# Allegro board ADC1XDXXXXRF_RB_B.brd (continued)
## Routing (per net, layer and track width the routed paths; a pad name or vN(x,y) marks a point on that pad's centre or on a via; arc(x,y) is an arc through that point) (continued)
V4_TCK: length 71.7
  TOP w0.102: v1(124.71,85.74) 125.21,86.25 U5.W12
  TOP w0.14: U14.20 v1(150.84,37.35)
  SIG1 w0.152: v1(124.71,85.74) 124.71,85.73 124.21,85.23 124.21,76.25 130.57,69.89 v1(141.96,69.89)
  SIG3 w0.152: v1(141.96,69.89) J6.4 146.72,51 148.12,51 150.84,48.27 v1(150.84,37.35)
V4_TDI: length 30.9
  TOP w0.14: U14.19 v1(150.16,37.85) ; R43.1 J6.5
  SIG3 w0.152: v1(150.16,37.85) 150.16,47.44 147.4,50.21 144.97,50.21 J6.5
V4_TDO: length 45.4
  TOP w0.102: v1(126.71,84.74) 126.22,85.23 U5.Y13
  SIG1 w0.152: v1(128.71,70.66) 128.72,70.66 129.99,69.39 v1(144.16,69.39) ; v1(128.71,77.39) 128.22,77.88 128.22,83.25 126.72,84.74 v1(126.71,84.74)
  SIG3 w0.152: v1(128.71,77.39) v1(128.71,70.66) ; J6.3 144.16,56.1 v1(144.16,69.39)
V4_TMS: length 73.7
  TOP w0.102: v1(123.71,84.74) 124.21,85.24 U5.Y11
  TOP w0.14: v1(152.18,36.86) 152.19,36.85 U14.21
  SIG1 w0.152: v1(123.71,76.01) 124.66,75.06 124.66,73.63 129.38,68.92 v1(147.05,68.92)
  SIG3 w0.152: v1(147.05,68.92) 147.05,55.76 J6.2 152.18,50.61 v1(152.18,36.86) ; v1(123.71,84.74) 123.71,84.74 123.21,84.24 123.21,76.51 v1(123.71,76.01)
VIN: length 73.2
  TOP w0.305: 90.35,158.32 90.35,156.06 v2(90.4,156.01) ; 90.35,158.32 90.35,159.2 90.34,159.2 U23.15 ; 90.35,158.32 90.99,158.32 91,158.33 91,159.36 90.99,159.37 U23.16 ; 109.43,195.94 108.76,195.94 108.76,195.93 U13.14 ; 109.43,195.94 109.76,195.94 ; 109.43,195.94 109.43,194.57 U13.13 ; 91,167.62 91,165.82 90.99,165.82 U23.5 ; 91,167.62 90.35,167.62 90.35,167.62 90.35,166.07 90.34,166.07 U23.6 ; 91,167.62 C269.1 ; 110.06,195.94 109.76,195.94 ; 110.06,195.94 110.71,195.94 U13.11 ; 110.06,195.94 110.06,194.57 U13.12 ; 109.76,195.94 109.76,196.11 ; U29.3 84.84,194.14 85.27,193.72 v2(85.27,192.24) U29.1 ; U16.4 131.28,194.61 131.18,194.72 131.18,195.45 131.4,195.67 131.93,195.67 ; 131.93,195.67 U16.3 ; 131.93,195.67 C193.1 ; v2(111.08,196.69) v2(108.46,196.69)
  TOP w0.508: U22.4 C229.1 ; C229.1 160.61,199.27 v2(160.61,199.26) ; C229.1 C228.1 ; C228.1 158.82,199 v2(158.81,198.99) ; C228.1 157.47,200.14 v2(157.47,200.15) ; C193.1 131.97,196.49 v2(131.98,196.5) 131.97,196.5 C192.1 131.97,198.58 v2(131.98,198.58) ; v2(189.27,200.1) 189.27,200.11 C207.1 ; 109.76,196.11 109.76,196.69 ; C207.1 C208.1 ; C207.1 190.61,199.08 v2(190.6,199.07) ; C208.1 192.35,199.11 v2(192.34,199.1) ; C208.1 U18.4 ; v2(89.67,168.95) 89.67,168.95 C269.1
  TOP w0.61: C159.1 109.74,197.67 ; 109.74,197.67 v2(111.08,197.67) v2(111.08,196.69) ; 109.74,197.67 v2(108.46,197.67) v2(108.46,196.69)
  TOP w0.635: v2(89.67,168.95) 88.14,168.95 C158.1 87.12,168.95 v2(85.59,168.95)
  TOP w0.762: v2(81.48,176.57) 81.49,176.57 L4.2 ; C160.1 85.35,177.82 v2(85.35,177.81) ; C160.1 84.04,176.52 v2(84.04,176.51) ; C160.1 82.47,177.82 v2(82.47,177.81) 82.46,177.82 L4.2 ; L4.2 81.49,178.96 v2(81.48,178.96)
  BOTTOM w0.305: v1(110.16,183.81) 109.83,184.13 109.83,184.24 109.72,184.36 R82.2
  BOTTOM w0.61: C187.1 190.78,199.1 v2(192.34,199.1) ; v2(189.27,200.1) 189.27,199.07 v2(190.6,199.07)
  vias: v2(88.49,157) v2(88.49,156.01)
VINI+: length 24
  TOP w0.102: v1(201.43,93.86) 201.16,94.13 199.74,94.13 U1.H1 ; J7.3 v1(209.27,79.07)
  SIG1 w0.102: v1(201.43,93.86) 201.73,94.16 202.12,94.16 207.96,85.22 207.96,85.21 208.03,85.14 208.16,85.02 209.13,85.02 209.27,84.88 v1(209.27,79.07)
VINI-: length 24
  TOP w0.102: v1(209.27,91.06) 209.27,91.06 211.03,91.06 211.2,90.89 J8.3 ; v1(201.43,94.69) 201.13,94.38 199.75,94.38 U1.J1
  SIG1 w0.102: v1(209.27,91.06) 209.27,85.36 209.13,85.22 208.24,85.22 208.18,85.29 208.13,85.33 202.23,94.36 201.76,94.36 v1(201.43,94.69)
VINQ+: length 24
  TOP w0.102: 211.2,114.52 v1(209.27,114.52) ; U1.N1 199.75,99.46 201.13,99.46 v1(201.43,99.77)
  TOP w0.14: J9.3 211.2,114.52
  SIG1 w0.102: v1(201.43,99.77) 201.76,99.44 201.96,99.44 202.09,99.64 208.02,108.72 209.17,108.72 209.27,108.82 v1(209.27,114.52)
VINQ-: length 24
  TOP w0.102: v1(201.43,98.91) 201.14,99.21 199.74,99.21 U1.M1 ; 211.2,102.7 v1(209.27,102.7)
  TOP w0.14: J10.3 211.2,102.7
  SIG1 w0.102: v1(201.43,98.91) 201.75,99.23 202.08,99.23 202.26,99.54 208.13,108.52 209.15,108.52 209.27,108.4 v1(209.27,102.7)
ADC_PWR: length 5.9
  TOP w0.102: R59.1 R58.2 137.72,82.74 137.23,82.25 U5.AC24
ADC_TDIODE+: length 53.2
  TOP w0.102: U1.E2 198,89.81 198.54,89.27 v1(198.58,89.27) ; v1(167.67,58.48) 167.37,58.18 167.16,58.18 167.06,58.28 167.06,58.62 166.95,58.72 C76.2 166.33,58.57 U8.7
  SIG1 w0.102: v1(167.67,58.48) 167.97,58.18 175.11,58.18 199.14,82.21 199.14,88.72 198.8,89.05 198.8,89.06 198.59,89.27 v1(198.58,89.27)
ADC_TDIODE-: length 130.2
  TOP w0.102: U5.G13 v1(126.71,97.75) ; U8.5 166.33,57.57 C76.1 166.95,57.43 167.06,57.53 167.06,57.87 167.11,57.92 167.42,57.92 v1(167.67,57.68) ; v1(197.33,90.45) 196.7,91.08 U1.F3
  SIG1 w0.102: v1(167.67,57.68) 167.97,57.98 175.19,57.98 199.34,82.13 199.34,88.8 199,89.14 199,89.46 198.74,89.72 198.06,89.72 v1(197.33,90.45)
  SIG2 w0.102: v1(167.67,57.68) 167.26,58.08 167.08,58.08 166.92,58.24 166.92,64.7 153.79,77.83 153.79,77.87 133.88,77.87 133.32,78.43 133.32,95.92 133.32,95.92 133.32,95.92 133.32,96.99 132.96,97.35 132.79,97.35 127.11,97.35 126.71,97.75 v1(126.71,97.75)
  BOTTOM w0.102: v1(167.67,57.68) 167.51,57.83 166.68,57.83 166.62,57.77 C75.1
CAL: length 157.6
  TOP w0.102: 138.71,80.77 138.24,81.24 U5.AD25
  TOP w0.14: 138.71,80.77 139.4,80.77 139.75,80.42 139.75,78.49 143.76,74.48 163.37,74.48 170.56,81.67 v1(191.13,81.67)
  SIG3 w0.14: v1(191.13,81.67) 192.9,83.43 192.9,91.55 192.9,91.55
  SIG3 w0.152: J4.29 154.83,144 154.83,141.87 163.22,133.47 185.89,133.47 186.94,132.42 186.94,114.87 189.79,112.02 193,112.02 194.17,110.86 194.17,92.82 v1(193.82,92.47) 192.9,91.55
  BOTTOM w0.152: R128.1 v1(193.82,92.47)
CALDLY: length 65
  TOP w0.14: J4.20 159.9,144.01 R113.2
  SIG3 w0.152: v1(193.44,113.92) 191.1,116.26 191.1,134.24 189.46,135.88 167.14,135.88 162.45,140.57 162.45,144 161.18,145.28 J4.20
  BOTTOM w0.14: v1(193.44,113.92) 193.44,112.16 R5.1
CALRUN: length 68.9
  TOP w0.102: 193.6,85.44 U1.B5 ; U5.AF23 136.22,78.69
  TOP w0.14: 193.6,85.44 193.6,80.85 192.71,79.96 172.85,79.96 165.97,73.08 141.71,73.08 136.22,78.58 136.22,78.69
CLK+: length 25.5
  TOP w0.102: C341.2 202.06,122.74 v1(201.98,122.66) ; v1(203.64,107.46) 203.34,107.16 203.34,106.73 202.15,105.54 198.45,105.54 U1.U2
  SIG3 w0.102: v1(203.64,107.46) 203.32,107.78 203.32,114.35 204.99,116.02 204.99,119.07 204.99,119.24 202.59,121.65 201.99,121.65 201.66,121.98 201.66,122.33 v1(201.98,122.66)
CLK-: length 24.9
  TOP w0.102: U1.V1 199.21,106.3 198.86,106.3 198.75,106.2 198.75,105.91 198.87,105.79 202.04,105.79 203.09,106.84 203.09,107.16 v1(202.79,107.46) ; v1(201.13,122.66) 201.05,122.74 C342.2
  SIG3 w0.102: v1(201.13,122.66) 201.45,122.33 201.45,121.9 201.9,121.45 201.92,121.45 202.5,121.45 204.79,119.16 204.79,116.11 203.11,114.43 203.11,114.26 203.11,107.78 v1(202.79,107.46)
CONF_CCLK: length 156.5
  TOP w0.14: R83.2 v1(147.21,41.94) R81.2 146,41.88 R84.1 131.88,41.88 v1(131.75,42.02) ; R17.2 107.63,31.6 108.03,31.99 114.03,31.99 114.9,32.87 130.62,32.87 v1(130.65,32.9) ; R31.1 v1(127.74,112.35)
  SIG3 w0.14: v1(130.65,32.9) 130.65,40.92 v1(131.75,42.02)
  SIG3 w0.152: v1(127.74,112.35) 130.49,112.35 132.73,114.58 153.25,114.58 v1(153.88,113.96)
  BOTTOM w0.14: v1(153.88,113.96) 153.88,55.05 147.21,48.38 v1(147.21,41.94)
CONF_DIN: length 211.5
  TOP w0.102: U5.G12 v1(124.71,98.75)
  TOP w0.14: U14.28 v1(172.81,36.85) ; U2.78 101.55,31.77 102.27,32.49 113.29,32.49 114.53,33.73 v1(128.09,33.73)
  SIG1 w0.152: v1(128.09,33.73) 169.69,33.73 v1(172.81,36.85)
  SIG2 w0.152: v1(124.71,112.88) 124.23,112.4 124.23,99.24 v1(124.71,98.75)
  SIG3 w0.152: v1(124.71,112.88) 130.06,112.88 132.19,115.01 158.24,115.01 v1(163.8,109.45)
  BOTTOM w0.14: v1(172.81,36.85) 168.73,40.92 168.73,104.52 v1(163.8,109.45)
CONF_DONE: length 198.2
  TOP w0.102: U5.H14 127.22,97.26 v1(127.71,97.75)
  TOP w0.14: v1(127.22,111.65) 118.74,111.65 118.4,111.99 117.21,111.99 R29.2 ; U14.13 150.7,40.85 149.14,39.28 v1(145.25,39.28) v1(124.08,39.28) ; U2.115 v1(91.23,47.21)
  SIG2 w0.152: v1(127.22,111.65) 127.22,98.24 127.71,97.75 v1(127.71,97.75)
  SIG3 w0.14: 111.81,46.21 92.23,46.21 v1(91.23,47.21)
  SIG3 w0.152: v1(127.22,111.65) 130.8,111.65 133.07,113.92 v1(152.66,113.92) ; 111.81,46.21 117.15,46.21 v1(124.08,39.28)
  BOTTOM w0.14: v1(145.25,39.28) 145.25,47.65 152.66,55.06 v1(152.66,113.92)
CONF_INITB: length 195.3
  TOP w0.102: U5.G15 128.22,98.26 v1(128.71,98.75)
  TOP w0.14: v1(149.67,42.02) 154.55,42.02 U14.11 ; R34.2 117.3,113.5 121.45,113.5 121.9,113.95 v1(128.25,113.95) ; v1(149.67,35.33) 114.7,35.33 113.07,33.7 105.06,33.7 104.45,33.09 102.13,33.09 101.31,32.27 U2.79
  SIG1 w0.152: v1(128.25,113.95) 128.25,108.68 127.23,107.66 127.23,101.96 128.22,100.97 128.22,99.25 v1(128.71,98.75)
  SIG3 w0.14: v1(154.19,116.23) 131.05,116.23 128.77,113.95 v1(128.25,113.95)
  SIG3 w0.152: v1(149.67,42.02) v1(149.67,35.33)
  BOTTOM w0.14: v1(149.67,42.02) 149.67,49.04 154.67,54.05 154.67,115.74 v1(154.19,116.23)
CS_N: length 85.7
  TOP w0.102: 120.22,78.82 U5.AF7
  TOP w0.14: v1(86.23,24.98) U2.42 ; v1(119.73,72.52) 119.74,72.52 120.22,73 120.22,78.82
  SIG1 w0.152: v1(92.29,72.25) 92.29,60.66 89.83,58.2 89.83,41.98 89.83,41.97 89.83,41.57 89.83,41.56 89.83,28.59 v1(86.23,24.98)
  SIG3 w0.152: v1(92.29,72.25) 92.55,72.52 v1(119.73,72.52)
CY_ADDR0: length 61
  TOP w0.102: 115.2,86.25 114.76,85.8
  TOP w0.14: 114.76,85.8 105.51,85.8 103.85,84.13 103.85,40.6 103.01,39.77 U2.94 ; U5.W2 115.2,86.25
CY_ADDR1: length 59.9
  TOP w0.102: U5.W1 113.39,86.25
  TOP w0.14: U2.95 102.58,40.27 103.35,41.04 103.35,84.86 104.74,86.25 113.39,86.25
CY_ADDR2: length 63.7
  TOP w0.102: v1(119.71,86.74) 119.22,87.23 U5.V6
  TOP w0.14: U2.96 102.19,40.77 102.82,41.4 v1(102.82,48.68)
  SIG1 w0.152: v1(119.71,86.74) 120.15,86.29 120.15,85.5 119.92,85.27 109.37,85.27 102.82,78.71 v1(102.82,48.68)
CY_ADDR3: length 65.1
  TOP w0.102: U5.V5 118.22,87.23 117.73,86.74 v1(117.71,86.74)
  TOP w0.14: v1(102.28,86.74) 102.29,86.74 102.29,41.68 101.88,41.27 U2.97
  BOTTOM w0.14: v1(102.28,86.74) 102.79,87.24 117.2,87.24 v1(117.71,86.74)
CY_ADDR4: length 67.4
  TOP w0.102: v1(119.71,85.74) 120.21,86.25 U5.W7
  TOP w0.14: U2.117 90.23,56.86 90.83,57.45 90.83,81.24 v1(90.83,81.25)
  SIG2 w0.152: v1(90.83,81.25) 91,81.25 95.02,85.27 119.24,85.27 119.71,85.74 v1(119.71,85.74)
CY_ADDR5: length 73
  TOP w0.102: U5.V7 120.21,87.24 v1(120.71,86.74)
  TOP w0.14: v1(91.03,86.69) 90.35,86 90.35,57.83 89.73,57.22 U2.118
  SIG2 w0.152: v1(91.03,86.69) 92.06,85.66 115.02,85.66 115.54,86.18 120.15,86.18 v1(120.71,86.74)
CY_ADDR6: length 68.8
  TOP w0.102: v1(116.71,85.74) 116.72,85.74 U5.W4
  TOP w0.14: v1(89.87,86.25) 89.87,86.25 89.87,58.12 89.23,57.48 U2.119
  SIG3 w0.152: v1(89.87,86.25) 116.19,86.25 v1(116.71,85.74)
CY_ADDR7: length 67.6
  TOP w0.102: v1(115.7,85.74) 115.72,85.74 U5.W3
  TOP w0.14: v1(89.31,85.78) 89.31,61.03 89.31,61.03 89.31,60.63 89.31,60.63 89.31,58.36 88.73,57.78 U2.120
  SIG3 w0.152: v1(115.7,85.74) 115.67,85.78 v1(89.31,85.78)
CY_ADDR8: length 72.8
  TOP w0.102: v1(118.71,85.74) 118.71,85.74 U5.W6
  TOP w0.14: v1(85.71,78.66) 85.69,78.64 85.69,45.56 U2.126
  SIG3 w0.152: v1(85.71,78.66) 116.66,78.66 118.24,80.24 118.24,85.27 v1(118.71,85.74)
CY_ADDR9: length 72.6
  TOP w0.102: v1(117.71,85.74) 117.71,85.74 117.72,85.74 U5.W5
  TOP w0.14: v1(85.23,79.27) U2.127
  SIG3 w0.152: v1(85.23,79.27) 116.23,79.27 117.21,80.26 117.21,85.23 v1(117.71,85.74)
CY_ADDR10: length 68.4
  TOP w0.102: 114.76,84.76 115.22,85.22 U5.Y2
  TOP w0.14: 114.76,84.76 110.36,84.76 v1(109.35,83.74) ; U2.128 84.73,51.1 84.73,51.1 v1(84.73,82.19)
  SIG3 w0.152: v1(109.35,83.74) 86.28,83.74 v1(84.73,82.19)
CY_ADDR11: length 80.8
  TOP w0.102: 113.77,85.24 U5.Y1
  TOP w0.14: U2.21 v1(88.33,33.77) ; 113.77,85.24 107.39,85.24 104.93,82.78
  TOP w0.152: v1(104.93,82.73) 104.93,82.78
  SIG1 w0.133: v1(88.33,33.77) 88.33,81.86 v1(88.54,82.07)
  SIG3 w0.152: v1(88.54,82.07) 89.2,82.73 v1(104.93,82.73)
CY_ADDR12: length 84.2
  TOP w0.102: v1(116.71,83.74) 116.72,83.74 U5.AA4
  TOP w0.14: U2.22 v1(87.82,33.27)
  SIG1 w0.133: v1(87.82,33.27) 87.82,82.44 v1(88.59,83.21)
  SIG3 w0.152: v1(116.71,83.74) 116.2,83.24 88.61,83.24 v1(88.59,83.21)
CY_ADDR13: length 84.4
  TOP w0.102: v1(115.71,83.75) 115.73,83.75 U5.AA3
  TOP w0.14: U2.23 v1(87.29,32.77)
  SIG1 w0.133: v1(88.62,84.28) 87.29,82.95 v1(87.29,32.77)
  SIG3 w0.152: v1(115.71,83.75) 115.18,84.28 v1(88.62,84.28)
CY_ADDR14: length 86.5
  TOP w0.102: U5.Y4 116.72,84.74 v1(116.71,84.74)
  TOP w0.14: U2.24 v1(86.77,32.27)
  SIG1 w0.133: v1(88.7,85.24) 86.77,83.31 v1(86.77,32.27)
  SIG3 w0.152: v1(88.7,85.24) 116.2,85.24 v1(116.71,84.74)
CY_ADDR15: length 85.7
  TOP w0.102: U5.Y3 115.72,84.74 v1(115.7,84.74)
  TOP w0.14: U2.25 v1(86.23,31.77)
  SIG1 w0.133: v1(86.23,31.77) 86.23,83.49 v1(87.48,84.73)
  SIG3 w0.152: v1(87.48,84.73) 115.7,84.73 v1(115.7,84.74)
CY_CTL3: length 83.2
  TOP w0.102: v1(127.72,79.74) 127.71,79.74 127.22,80.23 U5.AE14
  TOP w0.14: U2.66 113.11,25.77 113.55,26.21 126.82,26.21 127.07,26.46 v1(127.07,28.75)
  SIG1 w0.152: v1(127.07,28.75) 127.07,49.42 128.4,50.75 v1(128.4,55.57)
  SIG3 w0.152: v1(128.4,55.57) 128.23,55.74 128.23,79.23 v1(127.72,79.74)
CY_CTL4: length 80.4
  TOP w0.102: 126.7,79.77 U5.AE13
  TOP w0.14: 126.7,79.77 126.7,78.45 127.27,77.88 127.27,54.64 v1(127.6,54.31) ; U2.67 110.95,26.27 114.68,30 v1(126.55,30)
  SIG1 w0.152: v1(126.55,30) 126.55,49.94 127.6,50.99 v1(127.6,54.31)
CY_CTL5: length 61.9
  TOP w0.102: 122.73,79.76 U5.AE10
  TOP w0.14: v1(122.17,70.93) 122.73,71.49 122.73,79.76 ; U2.98 101.36,41.77 101.72,42.13 v1(101.72,70.93)
  SIG3 w0.152: v1(101.72,70.93) v1(122.17,70.93)
CY_DATA0: length 74.9
  TOP w0.102: 117.22,78.28 U5.AF4
  TOP w0.14: v1(114.77,74.69) 114.77,75.83 117.22,78.28 ; U2.59 v1(94.73,25.55)
  SIG1 w0.152: v1(94.73,25.55) 94.73,42.44 97.89,45.59 v1(97.89,74.69)
  SIG3 w0.152: v1(114.77,74.69) v1(97.89,74.69)
CY_DATA1: length 75
  TOP w0.102: 116.74,79.76 117.22,80.24 U5.AE4
  TOP w0.14: 116.74,79.76 116.74,78.41 114.09,75.76 v1(114.09,75.18) ; U2.60 v1(95.23,26.37)
  SIG1 w0.152: v1(98.48,75.18) 98.48,45.63 95.23,42.39 v1(95.23,26.37)
  SIG3 w0.152: v1(114.09,75.18) v1(98.48,75.18)
CY_DATA2: length 75.7
  TOP w0.102: U5.AD3 v1(115.71,80.73)
  TOP w0.14: U2.61 v1(95.74,27.34)
  SIG1 w0.152: v1(95.74,27.34) 95.74,42.36 98.93,45.55 v1(98.93,80.14)
  SIG3 w0.152: v1(98.93,80.14) 99.16,80.38 106.34,80.38 106.69,80.73 106.74,80.73 106.74,80.73 v1(115.71,80.73)
CY_DATA3: length 75.1
  TOP w0.102: v1(115.7,81.76) 115.74,81.76 U5.AC3
  TOP w0.14: U2.62 v1(96.23,26.36)
  SIG1 w0.133: 110.98,79.74 v1(110.86,79.74)
  SIG1 w0.152: v1(96.23,26.36) 96.23,40.58 99.9,44.24 v1(99.9,79.74) ; 110.98,79.74 113,81.76 v1(115.7,81.76)
  SIG3 w0.152: v1(110.86,79.74) v1(99.9,79.74)
CY_DATA4: length 75.5
  TOP w0.102: 119.22,78.8 U5.AF6
  TOP w0.14: v1(118.5,72.01) 119.22,72.73 119.22,78.8 ; U2.63 v1(96.73,25.55)
  SIG1 w0.152: v1(96.73,25.55) 96.73,40.52 100.48,44.26 v1(100.48,71.88)
  SIG3 w0.152: v1(118.5,72.01) 100.61,72.01 v1(100.48,71.88)
CY_DATA5: length 59.2
  TOP w0.102: 118.22,78.83 U5.AF5
  TOP w0.14: U2.86 v1(100.36,35.77) ; 118.22,78.83 118.22,74.78 114.22,70.77 114.22,58.57 112.16,56.52 v1(112.16,35.77)
  SIG3 w0.152: v1(100.36,35.77) v1(112.16,35.77)
CY_DATA6: length 64.5
  TOP w0.102: U5.AA7 120.21,84.24 v1(119.71,83.74)
  TOP w0.14: U2.87 v1(101.18,36.27)
  SIG1 w0.152: v1(111.46,36.27) 111.46,66.88 120.22,75.64 120.22,82.98 120.21,82.99 120.21,83.25 119.71,83.74 v1(119.71,83.74)
  SIG3 w0.152: v1(101.18,36.27) v1(111.46,36.27)
CY_DATA7: length 64.2
  TOP w0.102: U5.Y7 119.72,84.74 v1(119.71,84.74)
  TOP w0.14: v1(100.35,36.79) 99,36.79 U2.88
  SIG1 w0.152: v1(119.71,84.74) 119.22,84.25 119.22,83.98 119.23,83.97 119.23,75.47 110.72,66.96 v1(110.72,36.79)
  SIG3 w0.152: v1(110.72,36.79) v1(100.35,36.79)
CY_FD0: length 97.5
  TOP w0.102: v1(118.71,84.74) 118.72,84.74 U5.Y6
  TOP w0.14: U2.44 87.23,20.17 v1(87.23,20.17)
  SIG1 w0.152: v1(118.71,84.74) 118.26,84.3 118.26,83.54 117.96,83.24 111.4,83.26 107.24,79.1 107.24,20.42 106.47,19.66 v1(106.01,19.66)
  SIG3 w0.152: v1(106.01,19.66) 87.74,19.66 v1(87.23,20.17)
CY_FD1: length 94.8
  TOP w0.102: U5.Y5 117.72,84.74 v1(117.71,84.74)
  TOP w0.14: v1(87.73,20.83) 87.73,20.83 U2.45
  SIG1 w0.152: v1(117.71,84.74) 117.22,84.25 111.46,84.25 106.6,79.39 v1(106.6,20.53)
  SIG3 w0.152: v1(106.6,20.53) 106.33,20.27 88.29,20.27 v1(87.73,20.83)
CY_FD2: length 88.5
  TOP w0.102: 113.73,83.25 U5.AB1
  TOP w0.14: 113.73,83.25 111.03,83.25 107.86,80.08 v1(107.86,76.67) ; U2.46 v1(88.23,21.48)
  SIG1 w0.152: v1(107.86,21.32) v1(107.86,76.67)
  SIG3 w0.152: v1(88.23,21.48) 88.83,20.88 105.01,20.88 105.3,21.17 107.72,21.17 v1(107.86,21.32)
CY_FD3: length 86.7
  TOP w0.102: 113.75,84.24 U5.AA1
  TOP w0.14: U2.47 v1(88.73,22.16) ; v1(106.04,76.61) 106.04,79.47 110.81,84.24 113.75,84.24
  SIG1 w0.152: v1(105.97,22.16) 105.97,76.53 v1(106.04,76.61)
  SIG3 w0.152: v1(105.97,22.16) 105.16,22.16 104.49,21.49 89.4,21.49 v1(88.73,22.16)
CY_FD4: length 81.6
  TOP w0.102: v1(116.71,81.74) 116.72,81.74 U5.AC4
  TOP w0.14: v1(92.25,24.89) 92.23,24.87 U2.54
  SIG1 w0.152: v1(94.26,80.74) 94.26,49.68 92.25,47.67 v1(92.25,24.89)
  SIG3 w0.152: v1(116.71,81.74) 116.71,81.74 116.22,81.25 106.41,81.25 106.08,80.92 94.44,80.92 v1(94.26,80.74)
CY_FD5: length 81.9
  TOP w0.102: v1(116.71,82.74) 116.71,82.75 117.21,83.25 U5.AB4
  TOP w0.14: U2.55 v1(92.73,25.73)
  SIG1 w0.152: v1(92.73,25.73) 92.73,47.62 95.04,49.94 95.04,81.6 v1(95.28,81.84)
  SIG3 w0.152: v1(95.28,81.84) 105.51,81.84 105.93,82.26 116.23,82.26 116.71,82.74 v1(116.71,82.74)
CY_FD6: length 80.3
  TOP w0.102: v1(115.7,82.74) 115.71,82.74 116.22,83.25 U5.AB3
  TOP w0.14: v1(93.22,26.56) 93.23,26.55 U2.56
  SIG1 w0.152: v1(93.22,26.56) 93.22,47.54 95.62,49.94 95.62,81.47 v1(96.41,82.27)
  SIG3 w0.152: v1(96.41,82.27) 105.21,82.27 105.68,82.74 v1(115.7,82.74)
CY_FD7: length 78.5
  TOP w0.102: U5.AB2 115.22,83.24 114.78,82.8
  TOP w0.14: U2.57 93.73,25.66 v1(93.72,25.68) ; v1(111.02,81.74) 112.09,82.8 114.78,82.8
  SIG1 w0.152: v1(96.57,81.39) 96.07,80.89 96.07,46.92 93.72,44.56 v1(93.72,25.68)
  SIG3 w0.152: v1(96.57,81.39) 105.78,81.39 106.13,81.74 v1(111.02,81.74)
CY_FD8: length 57.2
  TOP w0.102: U5.AC5 117.72,81.74 v1(117.71,81.74)
  TOP w0.14: v1(99.4,76.83) 98.98,76.42 98.98,47.12
  TOP w0.152: 98.98,47.12 U2.102
  SIG1 w0.152: v1(117.74,77.65) 118.24,78.16 118.24,81.24 117.74,81.74 v1(117.71,81.74)
  SIG3 w0.152: v1(99.4,76.83) 99.74,77.17 117.26,77.17 v1(117.74,77.65)
CY_FD9: length 57.3
  TOP w0.102: U5.AB5 117.72,82.74 v1(117.71,82.74)
  TOP w0.14: U2.103 97.23,75.18 v1(97.69,75.64)
  SIG1 w0.152: v1(117.71,82.74) 117.71,82.73 117.2,82.22 117.2,80.47 116.24,79.5 v1(116.24,75.64)
  SIG3 w0.152: v1(116.24,75.64) v1(97.69,75.64)
CY_FD10: length 53.7
  TOP w0.102: U5.AC2 115.19,82.25 114.76,81.81
  TOP w0.14: 114.76,81.81 112.79,81.81 111.44,80.47 v1(111.44,77.65) ; v1(97.57,77.65) 96.73,76.81 U2.104
  SIG3 w0.152: v1(111.44,77.65) v1(97.57,77.65)
CY_FD11: length 53.1
  TOP w0.102: 113.82,82.25 U5.AC1
  TOP w0.14: v1(96.83,78.16) 96.24,77.57 U2.105 ; 113.82,82.25 112.44,82.25 110.27,80.08 v1(110.27,78.16)
  SIG3 w0.152: v1(110.27,78.16) v1(96.83,78.16)
CY_FD12: length 59.8
  TOP w0.102: 116.22,78.6 U5.AF3
  TOP w0.14: v1(88.81,59.31) 88.23,58.73 U2.121 ; 116.22,78.6 113.49,75.88 v1(113.49,59.31)
  SIG3 w0.133: v1(88.81,59.31) v1(113.49,59.31)
CY_FD13: length 60.7
  TOP w0.102: 115.75,79.78 116.21,80.24 U5.AE3
  TOP w0.14: v1(113,60.07) 113,76.04 115.72,78.77 115.72,79.76 115.75,79.78 ; v1(88.82,60.07) 87.73,58.99 U2.122
  SIG3 w0.133: v1(88.82,60.07) v1(113,60.07)
CY_FD14: length 61.8
  TOP w0.102: U5.AD2 115.2,81.24 114.71,80.75
  TOP w0.14: v1(88.83,60.83) 87.23,59.23 U2.123 ; v1(112.48,60.83) 112.48,79.66 113.56,80.75 114.71,80.75
  SIG3 w0.133: v1(88.83,60.83) v1(112.48,60.83)
CY_FD15: length 61.1
  TOP w0.102: 113.85,81.24 U5.AD1
  TOP w0.14: v1(88.83,61.62) 86.73,59.52 U2.124 ; 113.85,81.24 113.38,81.24 111.94,79.81 v1(111.94,61.62)
  SIG3 w0.133: v1(88.83,61.62) v1(111.94,61.62)
CY_ID0: length 72.3
  TOP w0.102: v1(121.71,83.74) 122.21,84.24 U5.AA9
  TOP w0.14: U2.72 110.61,28.77 v1(112.11,30.27)
  SIG1 w0.152: v1(121.71,83.74) 122.21,83.24 122.21,74.35 115.28,67.41 115.28,33.44 v1(112.11,30.27)
CY_ID1: length 73
  TOP w0.102: U5.Y9 122.21,85.24 v1(121.71,84.74)
  TOP w0.14: v1(109.76,29.27) 102.35,29.27 102.34,29.27 U2.73
  SIG1 w0.152: v1(117.71,76.83) 117.71,75.44 109.76,67.49 v1(109.76,29.27)
  SIG3 w0.152: v1(121.71,84.74) 121.71,84.74 121.23,84.26 119.43,84.26 119.22,84.05 119.22,81.97 119.23,81.96 119.23,81.56 119.22,81.56 119.22,80.98 119.23,80.97 119.23,80.57 119.22,80.57 119.22,78.34 v1(117.71,76.83)
CY_ID2: length 65.4
  TOP w0.102: v1(117.71,80.74) 117.71,80.75 118.2,81.24 U5.AD5
  TOP w0.14: U2.74 101.3,29.77 101.3,29.77 v1(109.15,29.77)
  SIG1 w0.152: v1(109.15,29.77) 109.15,67.64 117.21,75.7 117.21,79.21 117.71,79.71 v1(117.71,80.74)
CY_ID3: length 65.5
  TOP w0.102: v1(116.71,80.74) 116.73,80.74 117.22,81.23 U5.AD4
  TOP w0.14: v1(108.56,30.27) U2.75
  SIG1 w0.152: v1(116.71,80.74) 116.21,80.24 113.87,80.24 112.4,78.78 112.4,77.57 108.56,73.73 v1(108.56,30.27)
CY_REQ: length 53.6
  TOP w0.102: U5.AB7 120.2,83.25 119.71,82.75 v1(119.71,82.74)
  TOP w0.14: v1(93.22,78.16) 93.22,56.19 92.2,55.18 R13.2
  SIG2 w0.152: v1(93.22,78.16) 93.25,78.2 94.83,78.2 98.89,82.25 119.22,82.25 v1(119.71,82.74)
CY_VALID: length 65.7
  TOP w0.102: v1(121.72,81.74) 122.22,82.24 U5.AC9
  TOP w0.14: U2.114 v1(91.73,49.74)
  SIG1 w0.152: v1(92.74,73.6) 92.74,60.34 91.73,59.33 v1(91.73,49.74)
  SIG3 w0.152: v1(121.72,81.74) 121.72,81.74 121.23,81.25 121.23,79.98 121.23,79.98 121.23,79.58 121.23,79.58 121.23,74.19 120.65,73.6 v1(92.74,73.6)
DCLK_RST+: length 22.4
  TOP w0.102: v1(198.57,106.92) 197.97,106.32 U1.V2
  BOTTOM w0.102: R132.1 204.1,112.21 ; 204.1,112.21 204.1,113.06 206.72,115.67 206.72,119.52 207.34,120.15 R131.2 ; 204.1,112.21 204.1,110.51 ; R133.2 201.45,108.63 ; 201.45,108.63 200.29,108.63 199.12,107.45 198.68,107.45 198.57,107.34 v1(198.57,106.92) ; 201.45,108.63 203.72,108.63 204.1,109.01 204.1,110.51 ; 204.1,110.51 TP4.1
DCLK_RST-: length 22.1
  TOP w0.102: U1.W1 v1(198.63,108.2)
  BOTTOM w0.102: 203.9,110.52 203.9,109.1 203.64,108.83 201.45,108.83 ; 203.9,110.52 203.9,112.21 ; 203.9,110.52 TP3.1 ; R129.2 205.89,120.14 206.51,119.52 206.51,115.75 203.9,113.14 203.9,112.21 ; 203.9,112.21 R130.1 ; 201.45,108.83 200.21,108.83 199.03,107.65 198.73,107.65 198.63,107.75 v1(198.63,108.2) ; 201.45,108.83 R133.1
DCLKI+: length 65.9
  TOP w0.102: v1(159.34,98.05) 159.34,96.88 161.27,94.95 167.77,94.95 168.47,95.64 175.27,95.64 175.8,96.16 U1.K19 ; U5.A16 v1(128.71,104.76)
  SIG3 w0.102: v1(159.34,98.05) 157.45,99.93 157.45,102.26 158.2,103 159.31,103 159.41,103.1 159.41,103.31 159.31,103.41 158.2,103.41 157.98,103.63 157.98,104 158.2,104.22 159.31,104.22 159.41,104.32 159.41,104.53 159.31,104.63 158.2,104.63 157.98,104.85 157.98,106.25 157.44,106.79 128.94,106.79 128.55,106.4 128.55,104.91 v1(128.71,104.76)
DCLKI-: length 65.9
  TOP w0.102: U5.A15 v1(127.71,104.76) ; v1(160.1,98.05) 159.54,97.49 159.54,97.03 161.37,95.2 167.67,95.2 168.36,95.9 174.84,95.9 U1.K20
  SIG3 w0.102: v1(127.71,104.76) 128,104.76 128.35,105.11 128.35,106.49 128.86,106.99 157.52,106.99 158.18,106.33 158.18,104.93 158.29,104.83 159.39,104.83 159.61,104.61 159.61,104.24 159.39,104.02 158.29,104.02 158.18,103.92 158.18,103.71 158.29,103.61 159.39,103.61 159.61,103.39 159.61,103.02 159.39,102.8 158.29,102.8 157.66,102.17 157.66,100.02 159.2,98.48 159.67,98.48 v1(160.1,98.05)
DCLKQ+: length 52.1
  TOP w0.102: U5.A10 123.23,104.24 v1(123.74,104.76)
  SIG3 w0.102: v1(166.14,96.1) 166.32,96.28 166.32,97.21 162,101.53 162,103.3 157.24,108.06 125.86,108.06 123.74,105.95 v1(123.74,104.76)
DCLKQ+_OUT: length 49.7
  TOP w0.102: R162.3 163.53,96.1 162.71,96.91 161.89,96.91 161.67,97.13 161.67,98.68 142.32,118.03 142.32,122.63 138.07,126.87 136.5,126.87 136.4,126.77 DCLKQ+.1
DCLKQ-: length 52.1
  TOP w0.102: v1(123.74,103.76) 123.23,103.25 U5.B10
  SIG3 w0.102: v1(123.74,103.76) 123.74,104.19 123.32,104.6 123.32,104.92 123.54,105.14 123.54,106.04 125.77,108.27 157.32,108.27 162.2,103.39 162.2,101.62 165.84,97.98 v1(166.14,97.98)
DCLKQ-_OUT: length 49.7
  TOP w0.102: DCLKQ-.1 136.4,127.23 136.5,127.13 138.18,127.13 142.57,122.73 142.57,118.14 161.92,98.79 161.92,97.24 161.99,97.17 162.71,97.17 163.53,97.98 R161.3
DCLKQ_N: length 12.1
  TOP w0.102: U1.L20 174.84,97.17 174.33,97.17 174.08,97.42 174.08,97.89 173.82,98.15 173.55,98.15 173.29,97.89 173.29,97.42 173.04,97.17 165.66,97.17 R161.2
DCLKQ_P: length 12.1
  TOP w0.102: U1.L19 175.82,97.43 175.3,96.91 165.66,96.91 R162.2
DDRPHASE: length 64.1
  TOP w0.14: J4.17 162.44,144.01 R28.2
  SIG3 w0.152: J4.17 164.98,144.01 164.98,140.32 168.62,136.68 190.09,136.68 192.15,134.62 192.15,116.77 v1(193.44,115.48)
  BOTTOM w0.14: R3.1 195.02,113.91 v1(193.44,115.48)
DES: length 59.6
  TOP w0.14: R26.2 167.52,144 168.79,145.27 J4.11
  SIG3 w0.152: J4.11 168.79,145.28 170.06,144.01 170.06,140.67 172.22,138.51 191.07,138.51 194.06,135.52 v1(194.06,119.2)
  BOTTOM w0.14: R6.1 191.86,117 v1(194.06,119.2)
DI+0: length 67
  TOP w0.102: U1.B18 v1(178.28,85.37) ; U5.N23 v1(136.67,91.79)
  SIG1 w0.102: v1(136.67,91.79) 136.67,91.79 137.43,92.54 145.56,92.54 145.93,92.18 145.93,85.39 147.56,83.76 163.66,83.76 163.88,83.98 163.88,85.83 163.98,85.93 164.18,85.93 164.28,85.83 164.28,83.98 164.5,83.76 164.87,83.76 165.09,83.98 165.09,85.83 165.2,85.93 165.4,85.93 165.5,85.83 165.5,83.98 165.72,83.76 166.09,83.76 166.31,83.98 166.31,85.83 166.42,85.93 166.62,85.93 166.72,85.83 166.72,83.98 166.94,83.76 167.31,83.76 167.53,83.98 167.53,85.77 167.63,85.87 177.27,85.87 177.74,86.34 178.02,86.34 178.28,86.07 v1(178.28,85.37)
  BOTTOM w0.102: v1(178.28,85.37) R210.1
DI+1: length 67
  TOP w0.102: U5.M21 134.22,93.25 v1(134.72,92.75) ; v1(175.78,85.4) 176.38,86 U1.B19
  SIG2 w0.102: v1(175.78,85.4) 175.18,85.4 174.51,86.07 167.3,86.07 167.08,85.84 167.08,83.25 166.98,83.14 166.58,83.14 166.48,83.25 166.48,85.29 166.26,85.51 165.89,85.51 165.67,85.29 165.67,83.25 165.57,83.14 165.36,83.14 165.26,83.25 165.26,85.29 165.04,85.51 164.67,85.51 164.45,85.29 164.45,83.25 164.35,83.14 164.14,83.14 164.04,83.25 164.04,85.29 163.82,85.51 163.45,85.51 163.23,85.29 163.23,83.25 163.13,83.14 145.74,83.14 144.6,84.28 144.6,89.92 143.17,91.35 136.13,91.35 134.73,92.75 v1(134.72,92.75)
  BOTTOM w0.102: R213.1 175.31,84.81 175.31,84.96 175.75,85.4 v1(175.78,85.4)
DI+2: length 65.9
  TOP w0.102: U1.C19 176.38,87.27 v1(175.76,86.66) ; U5.M23 v1(136.72,93.75)
  SIG1 w0.102: v1(175.76,86.66) 174.71,86.66 174.32,87.05 163.33,87.05 163.11,86.83 163.11,84.55 163.01,84.45 162.81,84.45 162.71,84.55 162.71,86.86 162.49,87.08 162.11,87.08 161.89,86.86 161.89,84.55 161.79,84.45 161.59,84.45 161.49,84.55 161.49,86.86 161.27,87.08 160.9,87.08 160.68,86.86 160.68,84.55 160.57,84.45 160.37,84.45 160.27,84.55 160.27,86.86 160.05,87.08 159.68,87.08 159.46,86.86 159.46,84.55 159.35,84.45 148.37,84.45 147.16,85.66 147.16,92.75 146.64,93.26 137.21,93.26 v1(136.72,93.75)
DI+3: length 66
  TOP w0.102: v1(178.28,89.17) 177.65,88.54 U1.D18 ; v1(138.73,93.75) 138.23,93.25 U5.M25
  SIG1 w0.102: v1(178.28,89.17) 177.59,89.17 177.24,88.82 177.24,88.15 176.4,87.3 173.94,87.3 173.5,87.74 159.2,87.74 159.1,87.64 159.1,85.6 158.88,85.38 158.51,85.38 158.29,85.6 158.29,87.64 158.19,87.74 157.98,87.74 157.88,87.64 157.88,85.6 157.66,85.38 157.29,85.38 157.07,85.6 157.07,87.64 156.97,87.74 156.76,87.74 156.66,87.64 156.66,85.6 156.44,85.38 156.07,85.38 155.85,85.6 155.85,87.64 155.75,87.74 155.54,87.74 155.44,87.64 155.44,85.6 155.23,85.39 148.6,85.39 147.99,85.99 147.99,93.65 147.49,94.15 139.13,94.15 v1(138.73,93.75)
DI+4: length 65.9
  TOP w0.102: U5.L21 134.22,94.24 v1(134.72,93.75) ; U1.D19 176.38,88.54 v1(175.82,87.98)
  SIG2 w0.102: v1(175.82,87.98) 175.15,87.98 174.52,88.62 166.26,88.62 166.04,88.4 166.04,86.71 165.94,86.61 165.74,86.61 165.64,86.71 165.64,88.4 165.42,88.62 165.04,88.62 164.82,88.4 164.82,86.71 164.72,86.61 164.52,86.61 164.42,86.71 164.42,88.4 164.2,88.62 163.82,88.62 163.6,88.4 163.6,86.71 163.5,86.61 163.3,86.61 163.2,86.71 163.2,88.4 162.98,88.62 162.39,88.62 162.18,88.41 162.18,84.13 162.07,84.03 147.34,84.03 146.32,85.04 146.32,91.37 145.17,92.51 137.94,92.51 137.1,93.35 135.12,93.35 v1(134.72,93.75)
DI+5: length 66
  TOP w0.102: v1(137.75,94.75) 137.73,94.75 137.22,94.24 U5.L24 ; v1(175.78,89.22) 176.37,89.81 U1.E19
  SIG1 w0.102: v1(175.78,89.22) 175.06,88.51 154.99,88.51 154.88,88.41 154.88,86.09 154.66,85.86 154.29,85.86 154.07,86.09 154.07,88.41 153.97,88.51 153.77,88.51 153.66,88.41 153.66,86.09 153.44,85.86 153.07,85.86 152.85,86.09 152.85,88.41 152.75,88.51 152.55,88.51 152.45,88.41 152.45,86.09 152.23,85.86 151.85,85.86 151.63,86.09 151.63,88.41 151.53,88.51 151.33,88.51 151.23,88.41 151.23,86.09 151.01,85.86 149.25,85.86 148.79,86.32 148.79,94.65 148.29,95.15 138.15,95.15 v1(137.75,94.75)
DI+6: length 65.9
  TOP w0.102: U5.L26 139.26,94.24 v1(139.84,93.67) ; U1.F18 177.65,91.07 v1(177.07,90.49)
  SIG2 w0.102: v1(139.84,93.67) 140.35,93.67 141,93.02 141.02,93.02 141.02,93.02 146.86,93.02 147.51,92.37 147.51,85.63 148.43,84.71 156.02,84.71 156.24,84.93 156.24,86.59 156.34,86.7 156.54,86.7 156.65,86.59 156.65,84.93 156.87,84.71 157.24,84.71 157.46,84.93 157.46,86.59 157.56,86.7 157.76,86.7 157.86,86.59 157.86,84.93 158.08,84.71 158.46,84.71 158.68,84.93 158.68,86.59 158.78,86.7 158.98,86.7 159.08,86.59 159.08,84.93 159.3,84.71 159.68,84.71 159.9,84.93 159.9,86.59 160,86.7 160.2,86.7 160.3,86.59 160.3,84.93 160.52,84.71 160.95,84.71 161.16,84.92 161.16,89.14 161.26,89.24 173.45,89.24 173.91,89.7 176.28,89.7 177.07,90.49 v1(177.07,90.49)
DI+7: length 66
  TOP w0.102: v1(134.71,94.75) 135.21,95.24 U5.K22 ; U1.G17 v1(178.32,91.75)
  SIG2 w0.102: v1(178.32,91.75) 177.49,92.58 177.02,92.58 177.02,92.58 173.56,92.58 173.23,92.25 173.23,90.4 172.94,90.11 160.62,90.11 160.28,89.77 160.28,87.88 160.06,87.66 159.8,87.66 159.7,87.76 159.7,89.31 159.48,89.53 159.11,89.53 158.89,89.31 158.89,87.76 158.79,87.66 158.58,87.66 158.48,87.76 158.48,89.31 158.26,89.53 157.89,89.53 157.67,89.31 157.67,87.76 157.57,87.66 155.6,87.66 155.18,87.25 155.18,86.25 154.75,85.82 149.69,85.82 149.32,86.18 149.32,93.58 148.56,94.35 134.82,94.35 134.71,94.46 v1(134.71,94.75)
DI+8: length 66
  TOP w0.102: U5.K24 137.22,95.25 v1(137.72,95.75) ; U1.G19 v1(175.78,91.75)
  SIG1 w0.102: v1(137.72,95.75) 138.12,96.15 149.51,96.15 149.9,95.76 149.9,91.66 150.5,91.06 165.32,91.06 165.42,90.96 165.42,89.56 165.64,89.34 166.01,89.34 166.23,89.56 166.23,90.96 166.33,91.06 166.53,91.06 166.64,90.96 166.64,89.56 166.86,89.34 167.23,89.34 167.45,89.56 167.45,90.96 167.55,91.06 167.75,91.06 167.86,90.96 167.86,89.56 168.08,89.34 168.45,89.34 168.67,89.56 168.67,90.96 168.77,91.06 168.97,91.06 169.07,90.96 169.07,89.56 169.3,89.34 169.67,89.34 169.89,89.56 169.89,90.96 169.99,91.06 170.19,91.06 170.29,90.96 170.29,89.56 170.51,89.34 170.89,89.34 171.11,89.56 171.11,90.96 171.21,91.06 171.41,91.06 171.51,90.96 171.51,89.56 171.73,89.34 172.11,89.34 172.33,89.56 172.33,90.96 172.43,91.06 172.63,91.06 172.73,90.96 172.73,89.56 172.95,89.34 173.32,89.34 173.54,89.56 173.54,90.96 173.65,91.06 174.39,91.06 174.73,91.41 174.73,91.41 175.08,91.75 v1(175.78,91.75)
DI+9: length 65.9
  TOP w0.102: U1.H17 178.92,93.62 v1(178.31,93.01) ; U5.K26 v1(139.73,95.75)
  SIG2 w0.102: v1(139.73,95.75) 139.98,95.49 164.59,95.49 164.7,95.6 164.7,95.97 164.92,96.19 165.29,96.19 165.51,95.97 165.51,95.8 165.51,95.6 165.63,95.49 167.75,95.49 167.97,95.71 167.97,98.31 168.19,98.53 168.56,98.53 168.78,98.31 168.78,95.5 168.88,95.4 169.09,95.4 169.19,95.5 169.19,98.31 169.41,98.53 169.78,98.53 170,98.31 170,95.5 170.1,95.4 170.31,95.4 170.41,95.5 170.41,98.31 170.63,98.53 171,98.53 171.22,98.31 171.22,95.47 171.32,95.37 171.53,95.37 171.63,95.47 171.63,98.31 171.85,98.53 172.22,98.53 172.44,98.31 172.44,95.54 172.82,95.16 174.75,95.16 175.22,94.69 175.22,94.21 175.69,93.74 176.93,93.74 177.26,93.41 177.26,93.41 177.66,93.01 v1(178.31,93.01)
DI+10: length 66
  TOP w0.102: U1.H19 v1(175.77,93.01) ; v1(134.72,95.75) 134.22,96.25 U5.J21
  SIG2 w0.102: v1(134.72,95.75) 135.12,95.35 139.12,95.35 139.62,94.85 155.79,94.85 156.13,94.51 156.13,92.92 156.39,92.67 157.13,92.67 157.35,92.45 157.35,90.87 157.46,90.77 157.66,90.77 157.76,90.87 157.76,92.45 157.98,92.67 158.35,92.67 158.57,92.45 158.57,90.87 158.67,90.77 158.88,90.77 158.98,90.87 158.98,92.45 159.2,92.67 159.57,92.67 159.79,92.45 159.79,90.87 159.89,90.77 160.1,90.77 160.2,90.87 160.2,92.45 160.42,92.67 160.79,92.67 161.01,92.45 161.01,90.87 161.11,90.77 161.32,90.77 161.42,90.87 161.42,92.45 161.64,92.67 162.01,92.67 162.23,92.45 162.23,90.87 162.33,90.77 162.54,90.77 162.64,90.87 162.64,92.45 162.86,92.67 163.23,92.67 163.45,92.45 163.45,90.87 163.55,90.77 163.75,90.77 163.86,90.87 163.86,92.45 164.08,92.67 172.39,92.67 173.37,93.64 174.49,93.64 175.12,93.01 v1(175.77,93.01)
DI+11: length 66
  TOP w0.102: U5.J23 v1(136.73,96.75) ; U1.J18 177.65,94.89 v1(177.06,94.31)
  SIG1 w0.102: v1(177.06,94.31) 176.36,94.31 176.01,93.95 176,93.95 175.59,93.55 157.9,93.55 157.58,93.87 157.58,95.75 157.48,95.85 157.27,95.85 157.17,95.75 157.17,93.87 156.95,93.65 156.58,93.65 156.36,93.87 156.36,95.8 156.26,95.9 156.06,95.9 155.95,95.8 155.95,93.87 155.73,93.65 155.36,93.65 155.14,93.87 155.14,95.8 155.04,95.9 154.84,95.9 154.73,95.8 154.73,93.87 154.51,93.65 154.14,93.65 153.92,93.87 153.92,95.8 153.82,95.9 153.62,95.9 153.52,95.8 153.52,93.87 153.29,93.65 152.92,93.65 152.7,93.87 152.7,95.8 152.6,95.9 152.4,95.9 152.3,95.8 152.3,93.87 152.08,93.65 151.47,93.65 150.98,94.13 150.98,96.85 150.68,97.15 137.12,97.15 v1(136.73,96.75)
DI-0: length 67
  TOP w0.102: v1(178.28,86.64) U1.C17 ; v1(135.72,92.75) 135.22,92.25 U5.N22
  SIG1 w0.102: v1(135.72,92.75) 145.65,92.75 146.13,92.26 146.13,85.48 147.63,83.98 163.59,83.98 163.67,84.06 163.67,85.92 163.89,86.14 164.26,86.14 164.49,85.92 164.49,84.06 164.59,83.96 164.79,83.96 164.89,84.06 164.89,85.92 165.11,86.14 165.48,86.14 165.7,85.92 165.7,84.06 165.81,83.96 166.01,83.96 166.11,84.06 166.11,85.92 166.33,86.14 166.7,86.14 166.92,85.92 166.92,84.06 167.03,83.96 167.23,83.96 167.33,84.06 167.33,85.85 167.55,86.07 177.18,86.07 177.66,86.54 178.19,86.54 v1(178.28,86.64)
  BOTTOM w0.102: R209.1 v1(178.28,86.64) 177.83,87.1 177.7,87.1 R211.2
DI-1: length 67
  TOP w0.102: U5.M20 v1(133.72,92.75) ; U1.B20 175.11,86 v1(174.47,85.37)
  SIG2 w0.102: v1(174.47,85.37) 174.47,85.8 174.41,85.86 167.39,85.86 167.29,85.76 167.29,83.16 167.07,82.94 166.5,82.94 166.28,83.16 166.28,85.2 166.18,85.3 165.97,85.3 165.87,85.2 165.87,83.16 165.65,82.94 165.28,82.94 165.06,83.16 165.06,85.2 164.96,85.3 164.75,85.3 164.65,85.2 164.65,83.16 164.43,82.94 164.06,82.94 163.84,83.16 163.84,85.2 163.74,85.3 163.53,85.3 163.43,85.2 163.43,83.16 163.21,82.94 145.66,82.94 144.4,84.2 144.4,89.83 143.09,91.15 136.04,91.15 134.85,92.34 134.12,92.34 v1(133.72,92.75)
  BOTTOM w0.102: R214.2 174.04,84.81 174.04,84.94 v1(174.47,85.37)
DI-2: length 65.9
  TOP w0.102: U1.C20 175.11,87.27 174.31,86.48 v1(174.31,86.49) ; U5.M22 v1(135.72,93.75)
  SIG1 w0.102: v1(174.31,86.49) 174.31,86.74 174.21,86.85 163.42,86.85 163.32,86.75 163.32,84.46 163.1,84.24 162.72,84.24 162.5,84.46 162.5,86.77 162.4,86.88 162.2,86.88 162.1,86.77 162.1,84.46 161.88,84.24 161.51,84.24 161.28,84.46 161.28,86.77 161.18,86.88 160.98,86.88 160.88,86.77 160.88,84.46 160.66,84.24 160.29,84.24 160.07,84.46 160.07,86.77 159.96,86.88 159.76,86.88 159.66,86.77 159.66,84.46 159.44,84.24 148.28,84.24 146.95,85.57 146.95,92.67 146.56,93.06 137.12,93.06 136.84,93.35 136.46,93.35 136.06,93.75 v1(135.72,93.75)
DI-3: length 66
  TOP w0.102: U5.M24 137.23,93.25 v1(137.73,93.75) ; U1.E18 v1(177.03,89.2)
  SIG1 w0.102: v1(177.03,89.2) 177.03,88.23 176.31,87.51 174.02,87.51 173.58,87.95 159.12,87.95 158.9,87.73 158.9,85.68 158.8,85.58 158.59,85.58 158.49,85.68 158.49,87.73 158.27,87.95 157.9,87.95 157.68,87.73 157.68,85.68 157.58,85.58 157.37,85.58 157.27,85.68 157.27,87.73 157.05,87.95 156.68,87.95 156.46,87.73 156.46,85.68 156.36,85.58 156.15,85.58 156.05,85.68 156.05,87.73 155.83,87.95 155.46,87.95 155.24,87.73 155.24,85.68 155.15,85.59 148.68,85.59 148.19,86.08 148.19,93.74 147.58,94.35 139.05,94.35 139,94.3 138.99,94.3 138.85,94.16 138.56,94.16 138.15,93.75 v1(137.73,93.75)
DI-4: length 65.9
  TOP w0.102: U5.L20 133.22,94.24 v1(133.72,93.75) ; U1.D20 175.11,88.54 v1(174.53,87.97)
  SIG2 w0.102: v1(133.72,93.75) 134.12,93.35 134.82,93.35 135.03,93.15 137.02,93.15 137.86,92.31 145.09,92.31 146.12,91.28 146.12,84.96 147.25,83.82 162.16,83.82 162.38,84.05 162.38,88.32 162.48,88.41 162.89,88.41 162.99,88.31 162.99,86.62 163.21,86.4 163.59,86.4 163.81,86.62 163.81,88.31 163.91,88.41 164.11,88.41 164.21,88.31 164.21,86.62 164.43,86.4 164.81,86.4 165.03,86.62 165.03,88.31 165.13,88.41 165.33,88.41 165.43,88.31 165.43,86.62 165.65,86.4 166.03,86.4 166.25,86.62 166.25,88.31 166.35,88.41 174.42,88.41 174.53,88.3 v1(174.53,87.97)
DI-5: length 66
  TOP w0.102: v1(174.56,89.26) 175.11,89.81 U1.E20 ; v1(136.74,94.75) 136.72,94.75 136.22,94.25 U5.L23
  SIG1 w0.102: v1(174.56,89.26) 174.56,88.84 174.43,88.71 154.9,88.71 154.68,88.49 154.68,86.17 154.58,86.07 154.38,86.07 154.27,86.17 154.27,88.49 154.05,88.71 153.68,88.71 153.46,88.49 153.46,86.17 153.36,86.07 153.16,86.07 153.06,86.17 153.06,88.49 152.83,88.71 152.46,88.71 152.24,88.49 152.24,86.17 152.14,86.07 151.94,86.07 151.84,86.17 151.84,88.49 151.62,88.71 151.24,88.71 151.02,88.49 151.02,86.17 150.92,86.07 149.34,86.07 149,86.41 149,94.73 148.37,95.35 138.04,95.35 137.87,95.18 137.57,95.18 137.14,94.75 v1(136.74,94.75)
DI-6: length 66
  TOP w0.102: U5.M26 139.61,93.25 139.65,93.21 140.05,93.21 140.53,93.69 v1(140.96,93.69) ; U1.F19 176.37,91.08 v1(175.81,90.52)
  SIG2 w0.102: v1(140.96,93.69) 140.96,93.37 141.1,93.23 146.94,93.23 147.71,92.46 147.71,85.71 148.51,84.91 155.93,84.91 156.04,85.01 156.04,86.68 156.26,86.9 156.63,86.9 156.85,86.68 156.85,85.01 156.95,84.91 157.15,84.91 157.25,85.01 157.25,86.68 157.48,86.9 157.85,86.9 158.07,86.68 158.07,85.01 158.17,84.91 158.37,84.91 158.47,85.01 158.47,86.68 158.69,86.9 159.07,86.9 159.29,86.68 159.29,85.01 159.39,84.91 159.59,84.91 159.69,85.01 159.69,86.68 159.91,86.9 160.29,86.9 160.51,86.68 160.51,85.01 160.61,84.91 160.86,84.91 160.96,85.01 160.96,89.22 161.18,89.44 173.37,89.44 173.83,89.91 174.86,89.91 174.86,89.9 176.12,89.9 176.45,90.23 176.45,90.44 176.36,90.52 v1(175.81,90.52)
DI-7: length 65.8
  TOP w0.102: v1(133.73,94.75) 134.22,95.24 U5.K21 ; U1.G18 v1(177.04,91.74)
  SIG2 w0.102: v1(133.73,94.75) 134.12,94.75 134.72,94.15 148.47,94.15 149.12,93.5 149.12,86.1 149.61,85.61 154.84,85.61 155.39,86.16 155.39,87.17 155.68,87.46 157.65,87.46 157.87,87.68 157.87,89.22 157.97,89.32 158.18,89.32 158.28,89.22 158.28,87.68 158.5,87.46 158.87,87.46 159.09,87.68 159.09,89.22 159.19,89.32 159.4,89.32 159.5,89.22 159.5,87.68 159.72,87.46 160.14,87.46 160.48,87.8 160.48,89.68 160.71,89.91 173.03,89.91 173.43,90.31 173.43,92.16 173.64,92.38 176.93,92.38 177.04,92.27 v1(177.04,91.74)
DI-8: length 65.9
  TOP w0.102: U5.K23 136.22,95.25 v1(136.72,95.75) ; U1.G20 175.11,92.35 v1(174.53,91.77)
  SIG1 w0.102: v1(136.72,95.75) 137.02,95.75 137.21,95.94 137.21,95.94 137.43,96.16 137.84,96.16 138.04,96.35 149.59,96.35 150.11,95.84 150.11,91.74 150.58,91.27 165.4,91.27 165.62,91.05 165.62,89.65 165.72,89.55 165.92,89.55 166.03,89.65 166.03,91.05 166.25,91.27 166.62,91.27 166.84,91.05 166.84,89.65 166.94,89.55 167.14,89.55 167.25,89.65 167.25,91.05 167.47,91.27 167.84,91.27 168.06,91.05 168.06,89.65 168.16,89.55 168.36,89.55 168.46,89.65 168.46,91.05 168.69,91.27 169.06,91.27 169.28,91.05 169.28,89.65 169.38,89.55 169.58,89.55 169.68,89.65 169.68,91.05 169.9,91.27 170.28,91.27 170.5,91.05 170.5,89.65 170.6,89.55 170.8,89.55 170.9,89.65 170.9,91.05 171.12,91.27 171.5,91.27 171.72,91.05 171.72,89.65 171.82,89.55 172.02,89.55 172.12,89.65 172.12,91.05 172.34,91.27 172.71,91.27 172.94,91.05 172.94,89.65 173.04,89.55 173.24,89.55 173.34,89.65 173.34,91.05 173.56,91.27 174.3,91.27 174.53,91.49 v1(174.53,91.77)
DI-9: length 65.8
  TOP w0.102: v1(138.73,95.75) 138.22,95.24 U5.K25 ; U1.H18 v1(177.06,93.04)
  SIG2 w0.102: v1(177.06,93.04) 177.06,93.32 176.85,93.53 175.61,93.53 175.02,94.12 175.02,94.6 174.67,94.95 172.73,94.95 172.24,95.45 172.24,98.22 172.14,98.32 171.93,98.32 171.83,98.22 171.83,95.39 171.61,95.17 171.24,95.17 171.02,95.39 171.02,98.22 170.92,98.32 170.71,98.32 170.61,98.22 170.61,95.41 170.39,95.19 170.02,95.19 169.8,95.41 169.8,98.22 169.7,98.32 169.49,98.32 169.39,98.22 169.39,95.41 169.17,95.19 168.8,95.19 168.58,95.41 168.58,98.22 168.48,98.32 168.27,98.32 168.17,98.22 168.17,95.63 167.83,95.29 165.54,95.29 165.31,95.52 165.31,95.88 165.2,95.99 165,95.99 164.9,95.89 164.9,95.51 164.67,95.29 139.9,95.29 139.85,95.34 139.57,95.34 139.16,95.75 v1(138.73,95.75)
DI-10: length 65.9
  TOP w0.102: U5.J20 133.22,96.25 v1(133.72,95.75) ; U1.H20 v1(174.52,93.03)
  SIG2 w0.102: v1(174.52,93.03) 174.52,93.31 174.38,93.44 173.45,93.44 172.48,92.46 164.16,92.46 164.06,92.36 164.06,90.79 163.84,90.57 163.47,90.57 163.25,90.79 163.25,92.36 163.15,92.46 162.94,92.46 162.84,92.36 162.84,90.79 162.62,90.57 162.25,90.57 162.03,90.79 162.03,92.36 161.93,92.46 161.72,92.46 161.62,92.36 161.62,90.79 161.4,90.57 161.03,90.57 160.81,90.79 160.81,92.36 160.71,92.46 160.5,92.46 160.4,92.36 160.4,90.79 160.18,90.57 159.81,90.57 159.59,90.79 159.59,92.36 159.49,92.46 159.28,92.46 159.18,92.36 159.18,90.79 158.96,90.57 158.59,90.57 158.37,90.79 158.37,92.36 158.27,92.46 158.07,92.46 157.96,92.36 157.96,90.79 157.74,90.57 157.37,90.57 157.15,90.79 157.15,92.36 157.05,92.46 156.3,92.46 155.93,92.84 155.93,94.42 155.71,94.65 139.53,94.65 139.03,95.15 134.53,95.15 133.93,95.75 v1(133.72,95.75)
DI-11: length 65.9
  TOP w0.102: v1(135.73,96.75) 135.22,96.25 U5.J22 ; v1(175.8,94.32) 176.37,94.89 U1.J19
  SIG1 w0.102: v1(175.8,94.32) 175.8,94.04 175.51,93.75 157.99,93.75 157.78,93.95 157.78,95.83 157.56,96.05 157.19,96.05 156.97,95.83 156.97,93.95 156.87,93.85 156.66,93.85 156.56,93.95 156.56,95.88 156.34,96.1 155.97,96.1 155.75,95.88 155.75,93.95 155.65,93.85 155.45,93.85 155.34,93.95 155.34,95.88 155.12,96.1 154.75,96.1 154.53,95.88 154.53,93.95 154.43,93.85 154.23,93.85 154.12,93.95 154.12,95.88 153.9,96.1 153.53,96.1 153.31,95.88 153.31,93.95 153.21,93.85 153.01,93.85 152.91,93.95 152.91,95.88 152.68,96.1 152.31,96.1 152.09,95.88 152.09,93.95 151.99,93.85 151.55,93.85 151.19,94.22 151.19,96.93 150.76,97.35 136.33,97.35 v1(135.73,96.75)
DID+0: length 67
  TOP w0.102: U5.V26 v1(138.72,87.74) ; U1.A10 v1(188.44,84.1)
  SIG1 w0.102: v1(188.44,84.1) 188.44,83.14 184.97,79.67 144.83,79.67 140.43,84.07 140.43,84.38 141.55,85.51 141.55,85.65 141.41,85.8 141.27,85.8 140.14,84.67 139.83,84.67 139.56,84.93 139.56,85.24 140.85,86.53 140.85,86.7 140.71,86.84 140.59,86.84 139.28,85.53 138.97,85.53 138.29,86.21 138.29,86.98 138.72,87.41 v1(138.72,87.74)
  BOTTOM w0.102: R204.1 v1(188.44,84.1)
DID+1: length 67
  TOP w0.102: U1.C10 v1(188.44,86.64) ; U5.U25 v1(137.72,87.74)
  SIG1 w0.102: v1(137.72,87.74) 137.12,87.14 137.12,86.56 144.81,78.87 185.22,78.87 188.98,82.63 188.98,87.49 188.89,87.58 188.67,87.58 188.44,87.36 v1(188.44,86.64)
  BOTTOM w0.102: R206.2 v1(188.44,86.64) 188.01,86.21 187.88,86.21 R207.1
DID+2: length 65.8
  TOP w0.102: U1.B11 186.54,86.01 v1(185.96,86.58) ; v1(134.67,88.75) 134.22,89.2 U5.T21
  SIG2 w0.102: v1(185.96,86.58) 186,86.61 186.56,86.61 187.71,85.47 187.71,83.56 184.03,79.88 143.34,79.88 140.54,82.68 140.54,83.27 138.45,85.36 135.87,85.36 134.32,86.92 134.32,88.4 v1(134.67,88.75)
DID+3: length 66
  TOP w0.102: v1(184.65,85.36) 185.27,84.74 U1.A12 ; U5.T24 v1(137.72,88.75)
  SIG2 w0.102: v1(137.72,88.75) 137.72,88.74 137.32,88.34 137.32,86.21 137.46,86.08 139.65,86.08 139.87,85.86 139.87,85 139.97,84.9 140.18,84.9 140.28,85 140.28,85.86 140.5,86.08 141.23,86.08 141.5,85.81 141.5,83.13 144.03,80.6 180.37,80.6 180.47,80.7 180.47,81.44 180.69,81.66 181.06,81.66 181.28,81.44 181.28,80.7 181.38,80.6 181.58,80.6 181.69,80.7 181.69,81.44 181.91,81.66 182.28,81.66 182.5,81.44 182.5,80.7 182.6,80.6 182.89,80.6 185.64,83.35 185.64,85.07 185.52,85.2 185.51,85.2 185.35,85.36 v1(184.65,85.36)
DID+4: length 65.9
  TOP w0.102: v1(140.66,88.64) 139.82,88.64 U5.T26 ; v1(184.6,87.96) 184.6,87.94 185.27,87.27 U1.C12
  SIG1 w0.102: v1(140.66,88.64) 141.22,88.09 141.78,88.09 142.45,87.41 142.45,83.84 145.65,80.63 183.22,80.63 183.32,80.74 183.32,82.07 183.54,82.29 183.92,82.29 184.14,82.07 184.14,80.74 184.24,80.63 184.49,80.63 185.24,81.38 185.24,82.55 185.46,82.77 186.9,82.77 187,82.88 187,83.08 186.9,83.18 185.46,83.18 185.24,83.4 185.24,87.3 184.6,87.94 v1(184.6,87.96)
DID+5: length 65.9
  TOP w0.102: U5.R22 135.22,90.23 135.72,89.73 v1(135.72,89.72) ; U1.B13 v1(183.43,86.58)
  SIG3 w0.102: v1(183.43,86.58) 184.07,86.58 185.13,85.51 185.13,81.63 184.08,80.58 142.51,80.58 142.07,81.02 142.07,83.72 141.24,84.55 136.18,84.55 135.32,85.41 135.32,89.32 v1(135.72,89.72)
DID+6: length 65.9
  TOP w0.102: U1.A14 v1(183.3,84.16) ; v1(137.72,89.75) 137.23,90.24 U5.R24
  SIG3 w0.102: v1(183.3,84.16) 183.19,84.27 183.19,84.93 183.3,85.04 183.47,85.04 184.04,84.48 184.04,83.1 183.69,82.75 149.53,82.75 149.42,82.85 149.42,83.98 149.2,84.2 148.83,84.2 148.61,83.98 148.61,82.85 148.51,82.75 148.31,82.75 148.21,82.85 148.21,83.98 147.98,84.2 147.61,84.2 147.39,83.98 147.39,82.85 147.29,82.75 147.09,82.75 146.99,82.85 146.99,83.98 146.77,84.2 146.39,84.2 146.17,83.98 146.17,82.85 146.07,82.75 144.47,82.75 144.25,82.96 144.25,85.53 143.81,85.97 137.7,85.97 137.32,86.35 137.32,89.34 v1(137.72,89.75)
DID+7: length 65.9
  TOP w0.102: U5.R26 139.22,90.24 v1(139.72,89.75) ; v1(182.08,87.91) 182.72,87.27 U1.C14
  SIG2 w0.102: v1(139.72,89.75) 139.97,89.49 141.63,89.49 142.42,88.71 142.42,88 142.2,87.78 141.56,87.78 141.46,87.68 141.46,87.47 141.56,87.37 142.2,87.37 142.42,87.15 142.42,83.36 144.36,81.42 179.69,81.42 179.79,81.52 179.79,82 180.01,82.22 180.53,82.22 180.64,82.32 180.64,83.24 180.86,83.46 181.23,83.46 181.45,83.24 181.45,82.32 181.55,82.22 181.75,82.22 181.85,82.32 181.85,83.24 182.07,83.46 182.45,83.46 182.67,83.24 182.67,82.32 182.77,82.22 183.52,82.22 183.93,82.63 183.93,87.05 183.62,87.36 183.34,87.36 183.01,87.69 183.01,87.97 182.87,88.11 182.28,88.11 v1(182.08,87.91)
DID+8: length 65.9
  TOP w0.102: U1.B15 181.46,85.93 v1(182.06,85.33) ; U5.P23 136.22,91.24 v1(136.72,90.75)
  SIG1 w0.102: v1(136.72,90.75) 136.72,90.44 136.8,90.35 140.3,90.35 140.52,90.13 140.52,89.48 140.63,89.38 140.83,89.38 140.93,89.48 140.93,90.13 141.15,90.35 141.52,90.35 141.74,90.13 141.74,89.48 141.85,89.38 142.05,89.38 142.15,89.48 142.15,90.13 142.37,90.35 142.79,90.35 143.28,89.86 143.28,84.38 146.15,81.52 182.25,81.52 182.46,81.73 182.46,82.15 182.36,82.25 181.7,82.25 181.48,82.47 181.48,82.84 181.7,83.06 182.41,83.06 182.63,83.28 182.63,85.89 182.19,86.33 181.84,86.33 181.62,86.12 181.62,85.77 v1(182.06,85.33)
DID+9: length 66
  TOP w0.102: U1.A16 180.19,84.73 v1(180.83,85.37) ; U5.P25 v1(138.72,90.75)
  SIG1 w0.102: v1(180.83,85.37) 180.15,85.37 179.77,84.99 179.77,84.89 179.55,84.67 178.22,84.67 178.12,84.57 178.12,83.15 178.22,83.05 180.33,83.05 180.5,83.05 180.73,82.82 180.73,82.36 180.49,82.12 173.68,82.12 173.46,82.34 173.46,83.12 173.35,83.23 173.15,83.23 173.05,83.12 173.05,82.34 172.83,82.12 172.32,82.12 172.1,82.34 172.1,83.14 172,83.24 171.79,83.24 171.69,83.14 171.69,82.34 171.47,82.12 171.1,82.12 170.88,82.34 170.88,83.14 170.78,83.24 170.57,83.24 170.47,83.14 170.47,82.34 170.25,82.12 169.88,82.12 169.66,82.34 169.66,83.14 169.56,83.24 169.35,83.24 169.25,83.14 169.25,82.34 169.03,82.12 146.76,82.12 144.03,84.84 144.03,90.3 143.19,91.14 139.89,91.14 139.89,91.15 139.56,91.15 139.55,91.14 139.12,91.14 v1(138.72,90.75)
DID+10: length 65.8
  TOP w0.102: U5.N21 v1(134.72,91.75) ; v1(179.55,86.63) 178.92,86 U1.B17
  SIG2 w0.102: v1(179.55,86.63) 180.1,86.08 180.1,84.94 179.97,84.81 179.07,84.81 178.77,84.51 178.77,82.54 178.62,82.4 172.61,82.4 172.5,82.5 172.5,83.12 172.28,83.34 171.91,83.34 171.69,83.12 171.69,82.5 171.59,82.4 171.39,82.4 171.28,82.5 171.28,83.12 171.06,83.34 170.69,83.34 170.47,83.12 170.47,82.5 170.37,82.4 170.17,82.4 170.07,82.5 170.07,83.12 169.84,83.34 169.47,83.34 169.25,83.12 169.25,82.5 169.15,82.4 168.95,82.4 168.85,82.5 168.85,83.12 168.63,83.34 168.25,83.34 168.03,83.12 168.03,82.5 167.93,82.4 144.79,82.4 143.34,83.85 143.34,88.95 141.94,90.35 134.48,90.35 133.93,90.9 133.93,91.35 134.33,91.75 v1(134.72,91.75)
DID+11: length 66
  TOP w0.102: v1(138.72,91.75) 138.22,92.25 U5.N25 ; U1.A18 177.64,84.73 v1(177.01,84.11)
  SIG3 w0.102: v1(138.72,91.75) 139.13,92.15 148.86,92.15 151.07,89.94 151.07,84.56 151.62,84.01 167.87,84.01 168.09,84.23 168.09,85.94 168.19,86.03 168.39,86.03 168.49,85.93 168.49,84.21 168.72,83.98 169.09,83.98 169.31,84.2 169.31,85.94 169.41,86.03 169.61,86.03 169.71,85.93 169.71,84.21 169.94,83.98 170.31,83.98 170.53,84.2 170.53,85.94 170.62,86.03 170.83,86.03 170.93,85.93 170.93,84.21 171.16,83.98 171.53,83.98 171.75,84.2 171.75,85.94 171.84,86.03 172.05,86.03 172.15,85.93 172.15,84.2 172.37,83.98 172.74,83.98 172.96,84.2 172.96,85.93 173.06,86.03 173.27,86.03 173.37,85.93 173.37,83.74 173.67,83.44 175.7,83.44 176.36,84.11 v1(177.01,84.11)
DID-0: length 67
  TOP w0.102: v1(138.71,86.74) 138.22,87.23 U5.V25 ; U1.B10 v1(188.44,85.37)
  SIG1 w0.102: v1(188.44,85.37) 188.63,85.18 188.63,84.87 188.04,84.28 188.04,83.93 188.24,83.74 188.24,83.23 184.88,79.87 144.92,79.87 140.63,84.16 140.63,84.3 141.76,85.43 141.76,85.74 141.49,86 141.18,86 140.06,84.87 139.91,84.87 139.77,85.02 139.77,85.16 141.06,86.45 141.06,86.78 140.79,87.05 140.5,87.05 139.19,85.74 139.05,85.74 138.49,86.29 138.49,86.52 v1(138.71,86.74)
  BOTTOM w0.102: R205.2 187.88,84.94 188.14,84.94 R203.1 v1(188.44,85.37)
